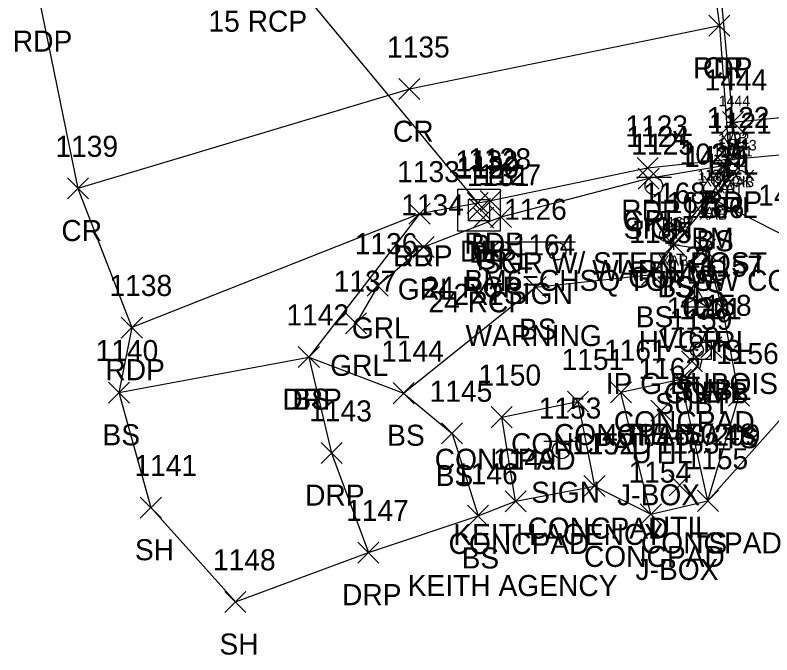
# Model space of a CAD drawing. Extents: x 1505684 to 1510253, y 730355 to 731397.
# Drawn here: x 1510031.8 to 1510103.6, y 730845.1 to 730905.9 of the extents above; entities that cross this region are included whole.
import ezdxf

# ---------------------------------------------------------------- set-up
doc = ezdxf.new("R2010")
doc.units = 0
for name, color, linetype in [('B_A', 7, 'Continuous'), ('B_I', 7, 'Continuous'), ('B_TIC', 7, 'Continuous'), ('BELB', 7, 'Continuous'), ('BSUBM', 7, 'Continuous'), ('C_A', 7, 'Continuous'), ('C_C', 7, 'Continuous'), ('C_I', 7, 'Continuous'), ('CBP', 7, 'Continuous'), ('CPBM', 7, 'Continuous'), ('CPSM', 7, 'Continuous'), ('D_A', 7, 'Continuous'), ('D_C', 7, 'Continuous'), ('D_I', 7, 'Continuous'), ('D_TIC', 7, 'Continuous'), ('DCP', 7, 'Continuous'), ('DS', 7, 'Continuous'), ('L_A', 7, 'Continuous'), ('L_C', 7, 'Continuous'), ('L_I', 7, 'Continuous'), ('L_TIC', 7, 'Continuous'), ('LARO', 7, 'Continuous'), ('LELB', 7, 'Continuous'), ('LS', 7, 'Continuous'), ('LSOGP', 7, 'Continuous'), ('P_A', 7, 'Continuous'), ('P_I', 7, 'Continuous'), ('P_TIC', 7, 'Continuous'), ('PET', 7, 'Continuous'), ('PRC', 7, 'Continuous'), ('R_A', 7, 'Continuous'), ('R_C', 7, 'Continuous'), ('R_I', 7, 'Continuous'), ('R_TIC', 7, 'Continuous'), ('RDP', 7, 'Continuous'), ('RGR', 7, 'Continuous'), ('S_A', 7, 'Continuous'), ('S_C', 7, 'Continuous'), ('S_I', 7, 'Continuous'), ('SSGN', 7, 'Continuous'), ('U_A', 7, 'Continuous'), ('U_C', 7, 'Continuous'), ('U_I', 7, 'Continuous'), ('U_TIC', 7, 'Continuous'), ('UDEFAULT', 7, 'Continuous'), ('UP', 7, 'Continuous'), ('UPGW', 7, 'Continuous')]:
    doc.layers.add(name, color=color, linetype=linetype)

msp = doc.modelspace()

# ---------------------------------------------------------------- linework, layer by layer
at = {"layer": 'B_TIC'}
for p, q in [((1510099.884, 730895.726), (1510099.96, 730895.726)), ((1510099.884, 730895.726), (1510099.96, 730895.726)), ((1510099.529, 730892.156), (1510099.604, 730892.156)), ((1510099.179, 730891.61), (1510099.254, 730891.61)), ((1510100.504, 730891.526), (1510100.58, 730891.526)), ((1510099.069, 730890.974), (1510099.145, 730890.974)), ((1510099.555, 730890.97), (1510099.631, 730890.97)), ((1510097.614, 730888.691), (1510097.69, 730888.691)), ((1510097.959, 730888.448), (1510098.035, 730888.448)), ((1510093.999, 730884.213), (1510094.074, 730884.213)), ((1510094.279, 730884.076), (1510094.354, 730884.076))]:
    msp.add_line(p, q, dxfattribs=at)
for points in [[(1510099.381, 730895.726), (1510100.381, 730895.726)], [(1510099.381, 730895.726), (1510100.381, 730895.726)], [(1510099.881, 730895.226), (1510099.881, 730896.226)], [(1510099.881, 730895.226), (1510099.881, 730896.226)], [(1510099.025, 730892.156), (1510100.025, 730892.156)], [(1510099.175, 730891.11), (1510099.175, 730892.11)], [(1510099.525, 730891.656), (1510099.525, 730892.656)], [(1510100.501, 730891.026), (1510100.501, 730892.026)], [(1510098.675, 730891.61), (1510099.675, 730891.61)], [(1510099.066, 730890.474), (1510099.066, 730891.474)], [(1510099.552, 730890.47), (1510099.552, 730891.47)], [(1510100.001, 730891.526), (1510101.001, 730891.526)], [(1510098.566, 730890.974), (1510099.566, 730890.974)], [(1510099.052, 730890.97), (1510100.052, 730890.97)], [(1510097.611, 730888.191), (1510097.611, 730889.191)], [(1510097.111, 730888.691), (1510098.111, 730888.691)], [(1510097.456, 730888.448), (1510098.456, 730888.448)], [(1510097.956, 730887.948), (1510097.956, 730888.948)], [(1510093.496, 730884.213), (1510094.496, 730884.213)], [(1510093.996, 730883.713), (1510093.996, 730884.713)], [(1510094.275, 730883.576), (1510094.275, 730884.576)], [(1510093.775, 730884.076), (1510094.775, 730884.076)]]:
    msp.add_lwpolyline(points, dxfattribs=at)
at = {"layer": 'BELB'}
msp.add_lwpolyline([(1510099.175, 730891.61), (1510099.525, 730892.156), (1510145.724, 730896.473), (1510191.184, 730900.384), (1510192.217, 730899.998), (1510192.409, 730899.895)], dxfattribs=at)
at = {"layer": 'BSUBM'}
for points in [[(1510088.464, 730929.774), (1510092.631, 730926.691), (1510094.249, 730925.597), (1510097.817, 730922.93), (1510097.711, 730918.36), (1510099.881, 730895.726)], [(1510094.275, 730884.076), (1510097.956, 730888.448), (1510100.501, 730891.526), (1510099.881, 730895.726)], [(1510093.996, 730884.213), (1510097.611, 730888.691), (1510099.552, 730890.97), (1510099.066, 730890.974)]]:
    msp.add_lwpolyline(points, dxfattribs=at)
at = {"layer": 'CBP'}
for radius in [0.625, 0.0833]:
    msp.add_circle((1510096.462, 730874.075), radius, dxfattribs=at)
at = {"layer": 'CPBM'}
for p, q in [((1510097.106, 730888.187), (1510097.106, 730889.187)), ((1510097.106, 730889.187), (1510098.106, 730889.187)), ((1510098.106, 730889.187), (1510098.106, 730888.187)), ((1510097.608, 730888.688), (1510097.608, 730888.688)), ((1510097.608, 730888.688), (1510097.608, 730888.688)), ((1510098.106, 730888.187), (1510097.106, 730888.187))]:
    msp.add_line(p, q, dxfattribs=at)
at = {"layer": 'CPSM'}
for p, q in [((1510094.984, 730878.174), (1510096.234, 730880.339)), ((1510097.484, 730878.174), (1510096.234, 730880.339)), ((1510096.235, 730878.895), (1510096.234, 730880.339)), ((1510094.984, 730878.174), (1510096.235, 730878.895)), ((1510096.235, 730878.895), (1510096.235, 730878.895)), ((1510096.235, 730878.895), (1510097.484, 730878.174)), ((1510094.984, 730878.174), (1510097.484, 730878.174))]:
    msp.add_line(p, q, dxfattribs=at)
at = {"layer": 'D_TIC'}
for points in [[(1510074.66, 730887.034), (1510076.66, 730889.034)], [(1510076.66, 730887.034), (1510074.66, 730889.034)], [(1510074.865, 730886.475), (1510076.865, 730888.475)], [(1510076.865, 730886.475), (1510074.865, 730888.475)], [(1510075.189, 730885.652), (1510077.189, 730887.652)], [(1510077.189, 730885.652), (1510075.189, 730887.652)]]:
    msp.add_lwpolyline(points, dxfattribs=at)
at = {"layer": 'DCP'}
msp.add_lwpolyline([(1510054.746, 730913.301), (1510075.66, 730888.034)], dxfattribs=at)
at = {"layer": 'DS'}
for p, q in [((1510073.788, 730889.356), (1510077.788, 730889.356)), ((1510073.788, 730885.356), (1510073.788, 730889.356)), ((1510077.788, 730889.356), (1510077.788, 730885.356)), ((1510074.788, 730886.356), (1510074.788, 730888.356)), ((1510074.788, 730888.356), (1510076.788, 730888.356)), ((1510076.788, 730888.356), (1510076.788, 730886.356)), ((1510075.793, 730887.358), (1510075.793, 730887.358)), ((1510075.793, 730887.358), (1510075.793, 730887.358)), ((1510076.788, 730886.356), (1510074.788, 730886.356)), ((1510077.788, 730885.356), (1510073.788, 730885.356))]:
    msp.add_line(p, q, dxfattribs=at)
at = {"layer": 'L_TIC'}
for points in [[(1510098.881, 730894.726), (1510100.881, 730896.726)], [(1510100.881, 730894.726), (1510098.881, 730896.726)], [(1510096.956, 730887.448), (1510098.956, 730889.448)], [(1510098.956, 730887.448), (1510096.956, 730889.448)], [(1510093.275, 730883.076), (1510095.275, 730885.076)], [(1510095.275, 730883.076), (1510093.275, 730885.076)], [(1510093.275, 730883.076), (1510095.275, 730885.076)], [(1510095.275, 730883.076), (1510093.275, 730885.076)], [(1510096.234, 730882.601), (1510098.234, 730884.601)], [(1510098.234, 730882.601), (1510096.234, 730884.601)], [(1510091.213, 730880.234), (1510093.213, 730882.234)], [(1510093.213, 730880.234), (1510091.213, 730882.234)], [(1510080.144, 730879.051), (1510082.144, 730881.051)], [(1510082.144, 730879.051), (1510080.144, 730881.051)], [(1510097.9, 730877.043), (1510099.9, 730879.043)], [(1510099.9, 730877.043), (1510097.9, 730879.043)], [(1510058.636, 730872.406), (1510060.636, 730874.406)], [(1510060.636, 730872.406), (1510058.636, 730874.406)], [(1510093.927, 730870.267), (1510095.927, 730872.267)], [(1510095.927, 730870.267), (1510093.927, 730872.267)], [(1510040.612, 730869.022), (1510042.612, 730871.022)], [(1510042.612, 730869.022), (1510040.612, 730871.022)], [(1510067.626, 730868.976), (1510069.626, 730870.976)], [(1510069.626, 730868.976), (1510067.626, 730870.976)], [(1510067.626, 730868.976), (1510069.626, 730870.976)], [(1510069.626, 730868.976), (1510067.626, 730870.976)], [(1510088.25, 730869.047), (1510090.25, 730871.047)], [(1510090.25, 730869.047), (1510088.25, 730871.047)], [(1510088.25, 730869.047), (1510090.25, 730871.047)], [(1510090.25, 730869.047), (1510088.25, 730871.047)], [(1510099.461, 730868.744), (1510101.461, 730870.744)], [(1510101.461, 730868.744), (1510099.461, 730870.744)], [(1510084.177, 730868.178), (1510086.177, 730870.178)], [(1510086.177, 730868.178), (1510084.177, 730870.178)], [(1510076.938, 730866.694), (1510078.938, 730868.694)], [(1510078.938, 730866.694), (1510076.938, 730868.694)], [(1510072.224, 730865.152), (1510074.224, 730867.152)], [(1510074.224, 730865.152), (1510072.224, 730867.152)], [(1510085.745, 730860.156), (1510087.745, 730862.156)], [(1510087.745, 730860.156), (1510085.745, 730862.156)], [(1510085.745, 730860.156), (1510087.745, 730862.156)], [(1510087.745, 730860.156), (1510085.745, 730862.156)], [(1510078.252, 730858.702), (1510080.252, 730860.702)], [(1510080.252, 730858.702), (1510078.252, 730860.702)], [(1510078.252, 730858.702), (1510080.252, 730860.702)], [(1510080.252, 730858.702), (1510078.252, 730860.702)], [(1510096.506, 730858.747), (1510098.506, 730860.747)], [(1510098.506, 730858.747), (1510096.506, 730860.747)], [(1510096.506, 730858.747), (1510098.506, 730860.747)], [(1510098.506, 730858.747), (1510096.506, 730860.747)], [(1510043.642, 730858.104), (1510045.642, 730860.104)], [(1510045.642, 730858.104), (1510043.642, 730860.104)], [(1510074.69, 730857.322), (1510076.69, 730859.322)], [(1510076.69, 730857.322), (1510074.69, 730859.322)], [(1510091.094, 730857.471), (1510093.094, 730859.471)], [(1510093.094, 730857.471), (1510091.094, 730859.471)], [(1510091.094, 730857.471), (1510093.094, 730859.471)], [(1510093.094, 730857.471), (1510091.094, 730859.471)], [(1510051.661, 730849.144), (1510053.661, 730851.144)], [(1510053.661, 730849.144), (1510051.661, 730851.144)]]:
    msp.add_lwpolyline(points, dxfattribs=at)
at = {"layer": 'LARO'}
msp.add_lwpolyline([(1510099.881, 730895.726), (1510107.98, 730896.493), (1510112.214, 730891.537)], dxfattribs=at)
at = {"layer": 'LELB'}
for points in [[(1510097.956, 730888.448), (1510105.059, 730884.781), (1510110.05, 730882.256), (1510113.646, 730877.864)], [(1510041.612, 730870.022), (1510059.636, 730873.406), (1510068.626, 730869.976), (1510081.144, 730880.051), (1510092.213, 730881.234), (1510094.275, 730884.076)], [(1510097.506, 730859.747), (1510100.461, 730869.744), (1510098.9, 730878.043), (1510097.234, 730883.601), (1510094.275, 730884.076)], [(1510068.626, 730869.976), (1510073.224, 730866.152), (1510075.69, 730858.322)]]:
    msp.add_lwpolyline(points, dxfattribs=at)
at = {"layer": 'LS'}
for points in [[(1510092.094, 730858.471), (1510097.506, 730859.747), (1510094.927, 730871.267), (1510089.25, 730870.047)], [(1510092.094, 730858.471), (1510089.25, 730870.047)], [(1510079.252, 730859.702), (1510077.938, 730867.694), (1510085.177, 730869.178), (1510086.745, 730861.156)], [(1510079.252, 730859.702), (1510086.745, 730861.156)]]:
    msp.add_lwpolyline(points, dxfattribs=at)
at = {"layer": 'LSOGP'}
msp.add_lwpolyline([(1510034.056, 730907.411), (1510037.72, 730889.421), (1510042.84, 730876.206), (1510041.612, 730870.022), (1510044.642, 730859.104), (1510052.661, 730850.144), (1510065.293, 730854.837), (1510075.69, 730858.322), (1510079.252, 730859.702), (1510086.745, 730861.156), (1510092.094, 730858.471), (1510097.506, 730859.747), (1510113.646, 730877.864), (1510115.997, 730887.658), (1510135.81, 730897.892), (1510165.212, 730879.843)], dxfattribs=at)
at = {"layer": 'P_TIC'}
for points in [[(1510097.597, 730903.875), (1510099.597, 730905.875)], [(1510099.597, 730903.875), (1510097.597, 730905.875)], [(1510097.597, 730903.875), (1510099.597, 730905.875)], [(1510099.597, 730903.875), (1510097.597, 730905.875)], [(1510068.181, 730897.854), (1510070.181, 730899.854)], [(1510070.181, 730897.854), (1510068.181, 730899.854)], [(1510098.525, 730891.156), (1510100.525, 730893.156)], [(1510100.525, 730891.156), (1510098.525, 730893.156)], [(1510090.79, 730890.356), (1510092.79, 730892.356)], [(1510092.79, 730890.356), (1510090.79, 730892.356)], [(1510036.72, 730888.421), (1510038.72, 730890.421)], [(1510038.72, 730888.421), (1510036.72, 730890.421)], [(1510075.903, 730887.234), (1510077.903, 730889.234)], [(1510077.903, 730887.234), (1510075.903, 730889.234)], [(1510069.14, 730886.015), (1510071.14, 730888.015)], [(1510071.14, 730886.015), (1510069.14, 730888.015)], [(1510041.84, 730875.206), (1510043.84, 730877.206)], [(1510043.84, 730875.206), (1510041.84, 730877.206)]]:
    msp.add_lwpolyline(points, dxfattribs=at)
at = {"layer": 'PET'}
msp.add_lwpolyline([(1510034.056, 730907.411), (1510054.481, 730913.105), (1510062.796, 730914.961), (1510073.319, 730917.02), (1510090.95, 730919.297), (1510096.423, 730920.568), (1510098.597, 730904.875), (1510099.525, 730892.156), (1510091.79, 730891.356), (1510076.903, 730888.234), (1510070.14, 730887.015), (1510042.84, 730876.206)], dxfattribs=at)
at = {"layer": 'PRC'}
msp.add_lwpolyline([(1510098.597, 730904.875), (1510069.181, 730898.854), (1510037.72, 730889.421)], dxfattribs=at)
at = {"layer": 'R_TIC'}
for points in [[(1510098.175, 730890.61), (1510100.175, 730892.61)], [(1510100.175, 730890.61), (1510098.175, 730892.61)], [(1510090.894, 730889.36), (1510092.894, 730891.36)], [(1510092.894, 730889.36), (1510090.894, 730891.36)], [(1510069.14, 730886.015), (1510071.14, 730888.015)], [(1510071.14, 730886.015), (1510069.14, 730888.015)], [(1510076.862, 730885.705), (1510078.862, 730887.705)], [(1510078.862, 730885.705), (1510076.862, 730887.705)], [(1510069.532, 730882.855), (1510071.532, 730884.855)], [(1510071.532, 730882.855), (1510069.532, 730884.855)], [(1510065.172, 730879.177), (1510067.172, 730881.177)], [(1510067.172, 730879.177), (1510065.172, 730881.177)], [(1510063.12, 730875.618), (1510065.12, 730877.618)], [(1510065.12, 730875.618), (1510063.12, 730877.618)], [(1510058.636, 730872.406), (1510060.636, 730874.406)], [(1510060.636, 730872.406), (1510058.636, 730874.406)], [(1510060.795, 730863.289), (1510062.795, 730865.289)], [(1510062.795, 730863.289), (1510060.795, 730865.289)], [(1510064.293, 730853.837), (1510066.293, 730855.837)], [(1510066.293, 730853.837), (1510064.293, 730855.837)]]:
    msp.add_lwpolyline(points, dxfattribs=at)
at = {"layer": 'RDP'}
msp.add_lwpolyline([(1510070.14, 730887.015), (1510059.636, 730873.406), (1510061.795, 730864.289), (1510065.293, 730854.837)], dxfattribs=at)
at = {"layer": 'RGR'}
msp.add_lwpolyline([(1510099.175, 730891.61), (1510091.894, 730890.36), (1510077.862, 730886.705), (1510070.532, 730883.855), (1510066.172, 730880.177), (1510064.12, 730876.618)], dxfattribs=at)
at = {"layer": 'SSGN'}
for p, q in [((1510090.734, 730890.487), (1510094.067, 730890.487)), ((1510092.381, 730889.654), (1510092.381, 730889.654)), ((1510076.33, 730884.363), (1510084.927, 730884.363)), ((1510080.352, 730883.459), (1510080.352, 730883.459)), ((1510081.948, 730865.414), (1510085.281, 730865.414)), ((1510083.595, 730864.581), (1510083.595, 730864.581))]:
    msp.add_line(p, q, dxfattribs=at)
for centre in [(1510092.381, 730889.654), (1510077.991, 730883.529), (1510083.205, 730883.459), (1510083.595, 730864.581)]:
    msp.add_circle(centre, 0.833, dxfattribs=at)
at = {"layer": 'U_TIC'}
for points in [[(1510096.83, 730873.318), (1510098.83, 730875.318)], [(1510098.83, 730873.318), (1510096.83, 730875.318)], [(1510095.005, 730871.994), (1510097.005, 730873.994)], [(1510097.005, 730871.994), (1510095.005, 730873.994)]]:
    msp.add_lwpolyline(points, dxfattribs=at)
at = {"layer": 'UDEFAULT'}
for points in [[(1510092.08, 730867.321), (1510094.08, 730869.321)], [(1510094.08, 730867.321), (1510092.08, 730869.321)], [(1510093.826, 730860.235), (1510095.826, 730862.235)], [(1510095.826, 730860.235), (1510093.826, 730862.235)]]:
    msp.add_lwpolyline(points, dxfattribs=at)
at = {"layer": 'UP'}
for p, q in [((1510097.227, 730875.666), (1510096.977, 730874.833)), ((1510096.144, 730873.166), (1510096.144, 730874.833)), ((1510096.144, 730874.833), (1510097.811, 730874.833)), ((1510097.811, 730874.833), (1510097.811, 730873.166)), ((1510096.977, 730874), (1510096.977, 730874)), ((1510097.811, 730873.166), (1510096.144, 730873.166)), ((1510096.727, 730872.333), (1510096.977, 730873.166))]:
    msp.add_line(p, q, dxfattribs=at)
msp.add_circle((1510096.977, 730874), 0.833, dxfattribs=at)
at = {"layer": 'UPGW'}
for radius in [0.625, 0.0833]:
    msp.add_circle((1510093.55, 730884.978), radius, dxfattribs=at)

# ---------------------------------------------------------------- texts
at = {"layer": 'B_A'}
for s, p in [('XAB', (1510098.601, 730893.726)), ('XAB', (1510098.601, 730893.726)), ('XDECK', (1510097.018, 730889.61)), ('XDECK', (1510097.368, 730890.156)), ('XAT', (1510097.77, 730888.974)), ('XAT', (1510098.256, 730888.97)), ('XAB', (1510099.221, 730889.526)), ('XAT', (1510096.316, 730886.691)), ('XAB', (1510096.676, 730886.448)), ('XAT', (1510092.7, 730882.213)), ('XAB', (1510092.996, 730882.076))]:
    msp.add_text(s, height=1, dxfattribs=at).set_placement(p)
at = {"layer": 'B_I'}
for s, p in [('1444', (1510098.534, 730897.226)), ('1444', (1510098.534, 730897.226)), ('1122', (1510098.462, 730893.656)), ('1172', (1510098.003, 730892.474)), ('1121', (1510098.396, 730893.11)), ('1171', (1510098.772, 730892.47)), ('1443', (1510099.154, 730893.026)), ('1170', (1510096.505, 730890.191)), ('1439', (1510096.605, 730889.948)), ('1169', (1510092.905, 730885.713)), ('1167', (1510093.189, 730885.576))]:
    msp.add_text(s, height=1, dxfattribs=at).set_placement(p)
at = {"layer": 'C_A'}
for s, p in [('BM', (1510095.923, 730883.688)), ('HVCTRL', (1510090.927, 730873.895)), ('TIE', (1510094.541, 730869.075))]:
    msp.add_text(s, height=2, dxfattribs=at).set_placement(p)
at = {"layer": 'C_C'}
for s, p in [('BM6=CHSQ TOP SW CONC WING', (1510074.404, 730879.688)), ('IP G.DUBOIS', (1510087.809, 730869.895)), ('TIE=50.48', (1510089.612, 730865.075))]:
    msp.add_text(s, height=2, dxfattribs=at).set_placement(p)
at = {"layer": 'C_I'}
for s, p in [('1029', (1510094.829, 730891.688)), ('21', (1510095.337, 730881.895)), ('1020', (1510093.604, 730877.075))]:
    msp.add_text(s, height=2, dxfattribs=at).set_placement(p)
at = {"layer": 'D_A'}
for s, p in [('P', (1510075.037, 730883.034)), ('DIB', (1510073.968, 730882.475)), ('DI', (1510074.848, 730882.358)), ('P', (1510075.567, 730881.652))]:
    msp.add_text(s, height=2, dxfattribs=at).set_placement(p)
at = {"layer": 'D_C'}
for s, p in [('15 RCP', (1510050.108, 730904.301)), ('24 RCP', (1510070.455, 730879.034)), ('2X2', (1510073.368, 730878.358)), ('24 RCP', (1510070.984, 730877.652))]:
    msp.add_text(s, height=2, dxfattribs=at).set_placement(p)
at = {"layer": 'D_I'}
for s, p in [('1132', (1510073.534, 730891.034)), ('1130', (1510073.653, 730890.475)), ('1129', (1510073.659, 730890.358)), ('1131', (1510074.63, 730889.652))]:
    msp.add_text(s, height=2, dxfattribs=at).set_placement(p)
at = {"layer": 'L_A'}
for s, p in [('LEL', (1510097.519, 730890.726)), ('BS', (1510096.397, 730883.448)), ('TS', (1510092.685, 730879.076)), ('BS', (1510092.716, 730879.076)), ('TS', (1510095.643, 730878.601)), ('BS', (1510090.654, 730876.234)), ('BS', (1510079.585, 730875.051)), ('TS', (1510097.309, 730873.043)), ('BS', (1510058.077, 730868.406)), ('CONCPAD', (1510088.573, 730866.267)), ('BS', (1510040.053, 730865.022)), ('BS', (1510067.067, 730864.976)), ('BS', (1510067.067, 730864.976)), ('CONCPAD', (1510082.896, 730865.047)), ('CONCPAD', (1510082.896, 730865.047)), ('CONCPAD', (1510078.823, 730864.178)), ('TS', (1510098.87, 730864.744)), ('CONCPAD', (1510071.583, 730862.694)), ('BS', (1510071.665, 730861.152)), ('CONCPAD', (1510080.39, 730856.156)), ('CONCPAD', (1510080.39, 730856.156)), ('SH', (1510043.13, 730854.104)), ('CONCPAD', (1510072.898, 730854.702)), ('CONCPAD', (1510072.898, 730854.702)), ('CONCPAD', (1510091.152, 730854.747)), ('TS', (1510095.916, 730854.747)), ('CONCPAD', (1510085.74, 730853.471)), ('CONCPAD', (1510085.74, 730853.471)), ('BS', (1510074.131, 730853.322)), ('SH', (1510051.149, 730845.144))]:
    msp.add_text(s, height=2, dxfattribs=at).set_placement(p)
at = {"layer": 'L_C'}
msp.add_text('KEITH AGENCY', height=2, dxfattribs=at).set_placement((1510069.016, 730850.702))
msp.add_text('KEITH AGENCY', height=2, dxfattribs=at).set_placement((1510069.016, 730850.702))
at = {"layer": 'L_I'}
for s, p in [('1444', (1510097.188, 730898.726)), ('1439', (1510095.255, 730891.448)), ('1440', (1510102.279, 730887.781)), ('1167', (1510092.102, 730887.076)), ('1167', (1510092.102, 730887.076)), ('1166', (1510095.005, 730886.601)), ('1165', (1510090.04, 730884.234)), ('1164', (1510078.971, 730883.051)), ('1157', (1510096.774, 730881.043)), ('1142', (1510057.51, 730876.406)), ('1160', (1510092.667, 730874.267)), ('1140', (1510039.4, 730873.022)), ('1144', (1510066.5, 730872.976)), ('1144', (1510066.5, 730872.976)), ('1161', (1510087.644, 730873.047)), ('1161', (1510087.644, 730873.047)), ('1151', (1510083.618, 730872.178)), ('1156', (1510098.28, 730872.744)), ('1150', (1510075.725, 730870.694)), ('1145', (1510071.098, 730869.152)), ('1152', (1510084.619, 730864.156)), ('1152', (1510084.619, 730864.156)), ('1149', (1510077.119, 730862.702)), ('1149', (1510077.119, 730862.702)), ('1155', (1510095.38, 730862.747)), ('1155', (1510095.38, 730862.747)), ('1141', (1510043.083, 730862.104)), ('1146', (1510073.509, 730861.322)), ('1154', (1510089.968, 730861.471)), ('1154', (1510089.968, 730861.471)), ('1148', (1510050.535, 730853.144))]:
    msp.add_text(s, height=2, dxfattribs=at).set_placement(p)
at = {"layer": 'P_A'}
for s, p in [('RDP', (1510031.545, 730902.411)), ('RDP', (1510096.086, 730899.875)), ('CR', (1510097.03, 730899.875)), ('CR', (1510067.614, 730893.854)), ('RDP', (1510097.014, 730887.156)), ('RDP', (1510089.278, 730886.356)), ('CR', (1510036.153, 730884.421)), ('RDP', (1510074.391, 730883.234)), ('RDP', (1510067.628, 730882.015)), ('RDP', (1510040.328, 730871.206))]:
    msp.add_text(s, height=2, dxfattribs=at).set_placement(p)
at = {"layer": 'P_I'}
for s, p in [('1135', (1510067.055, 730901.854)), ('1122', (1510097.399, 730895.156)), ('1123', (1510089.664, 730894.356)), ('1139', (1510035.586, 730892.421)), ('1128', (1510074.777, 730891.234)), ('1133', (1510068.014, 730890.015)), ('1138', (1510040.714, 730879.206))]:
    msp.add_text(s, height=2, dxfattribs=at).set_placement(p)
at = {"layer": 'R_A'}
for s, p in [('GRL', (1510096.719, 730886.61)), ('GRL', (1510089.437, 730885.36)), ('DRP', (1510067.628, 730882.015)), ('GRL', (1510075.405, 730881.705)), ('GRL', (1510068.075, 730878.855)), ('GRL', (1510063.716, 730875.177)), ('GRL', (1510061.664, 730871.618)), ('DRP', (1510057.124, 730868.406)), ('DRP', (1510059.283, 730859.289)), ('DRP', (1510062.781, 730849.837))]:
    msp.add_text(s, height=2, dxfattribs=at).set_placement(p)
at = {"layer": 'R_C'}
msp.add_text('SGR W/ STEEL POST', height=2, dxfattribs=at).set_placement((1510076.059, 730881.36))
at = {"layer": 'R_I'}
for s, p in [('1121', (1510097.616, 730894.61)), ('1124', (1510089.768, 730893.36)), ('1133', (1510068.014, 730890.015)), ('1127', (1510075.736, 730889.705)), ('1134', (1510068.406, 730886.855)), ('1136', (1510063.991, 730883.177)), ('1137', (1510061.994, 730879.618)), ('1142', (1510057.51, 730876.406)), ('1143', (1510059.669, 730867.289)), ('1147', (1510063.167, 730857.837))]:
    msp.add_text(s, height=2, dxfattribs=at).set_placement(p)
at = {"layer": 'S_A'}
for s, p in [('SIGN', (1510089.519, 730884.634)), ('TSIGN', (1510076.527, 730878.441)), ('SIGN', (1510080.733, 730859.561))]:
    msp.add_text(s, height=2, dxfattribs=at).set_placement(p)
at = {"layer": 'S_C'}
for s, p in [('WARNING', (1510086.527, 730880.634)), ('WARNING', (1510074.512, 730874.441)), ('KEITH AGENCY', (1510073.339, 730855.561))]:
    msp.add_text(s, height=2, dxfattribs=at).set_placement(p)
at = {"layer": 'S_I'}
for s, p in [('1125', (1510090.235, 730892.634)), ('1126', (1510078.165, 730886.441)), ('1153', (1510081.449, 730867.561))]:
    msp.add_text(s, height=2, dxfattribs=at).set_placement(p)
at = {"layer": 'U_A'}
for s, p in [('GUYW', (1510089.943, 730879.978)), ('SUBE', (1510094.365, 730869.318)), ('COMB', (1510093.363, 730869)), ('SUBT', (1510092.501, 730867.994)), ('UTIL', (1510090.245, 730863.321)), ('UTIL', (1510091.991, 730856.235))]:
    msp.add_text(s, height=2, dxfattribs=at).set_placement(p)
at = {"layer": 'U_C'}
for s, p in [('40T/160/209', (1510087.473, 730865)), ('J-BOX', (1510088.891, 730859.321)), ('J-BOX', (1510090.637, 730852.235))]:
    msp.add_text(s, height=2, dxfattribs=at).set_placement(p)
at = {"layer": 'U_I'}
for s, p in [('1168', (1510091.376, 730887.978)), ('1158', (1510095.704, 730877.318)), ('1021', (1510094.773, 730877)), ('1159', (1510093.871, 730875.994)), ('1162', (1510090.907, 730871.321)), ('1163', (1510092.652, 730864.235))]:
    msp.add_text(s, height=2, dxfattribs=at).set_placement(p)

doc.saveas('drawing.dxf')
